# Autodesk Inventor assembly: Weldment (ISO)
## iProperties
Length Units: 11269
Angle Units: 11283
Time Units: 11279
Mass Units: 11290
Length Display Precision: 3
Angle Display Precision: 2
Part Number: Weldment (ISO)
Document SubType Name: Weldment
Created: 2002-06
Designer: smithga
Part Number: support meule
Created: 2005-01
Designer: LEGERET Philippe
Material: Aluminum soudé-6061
Control State: 0
Master: False
Shininess: 64.0
Angle Units: 11279
Time Units: 11290
Mass Units: 11283
Compacted: True
Density: 0.0
Volumn: 0.0
Area: 0.0
PropertySet Name: Model Information
Author: LEGERET Philippe
